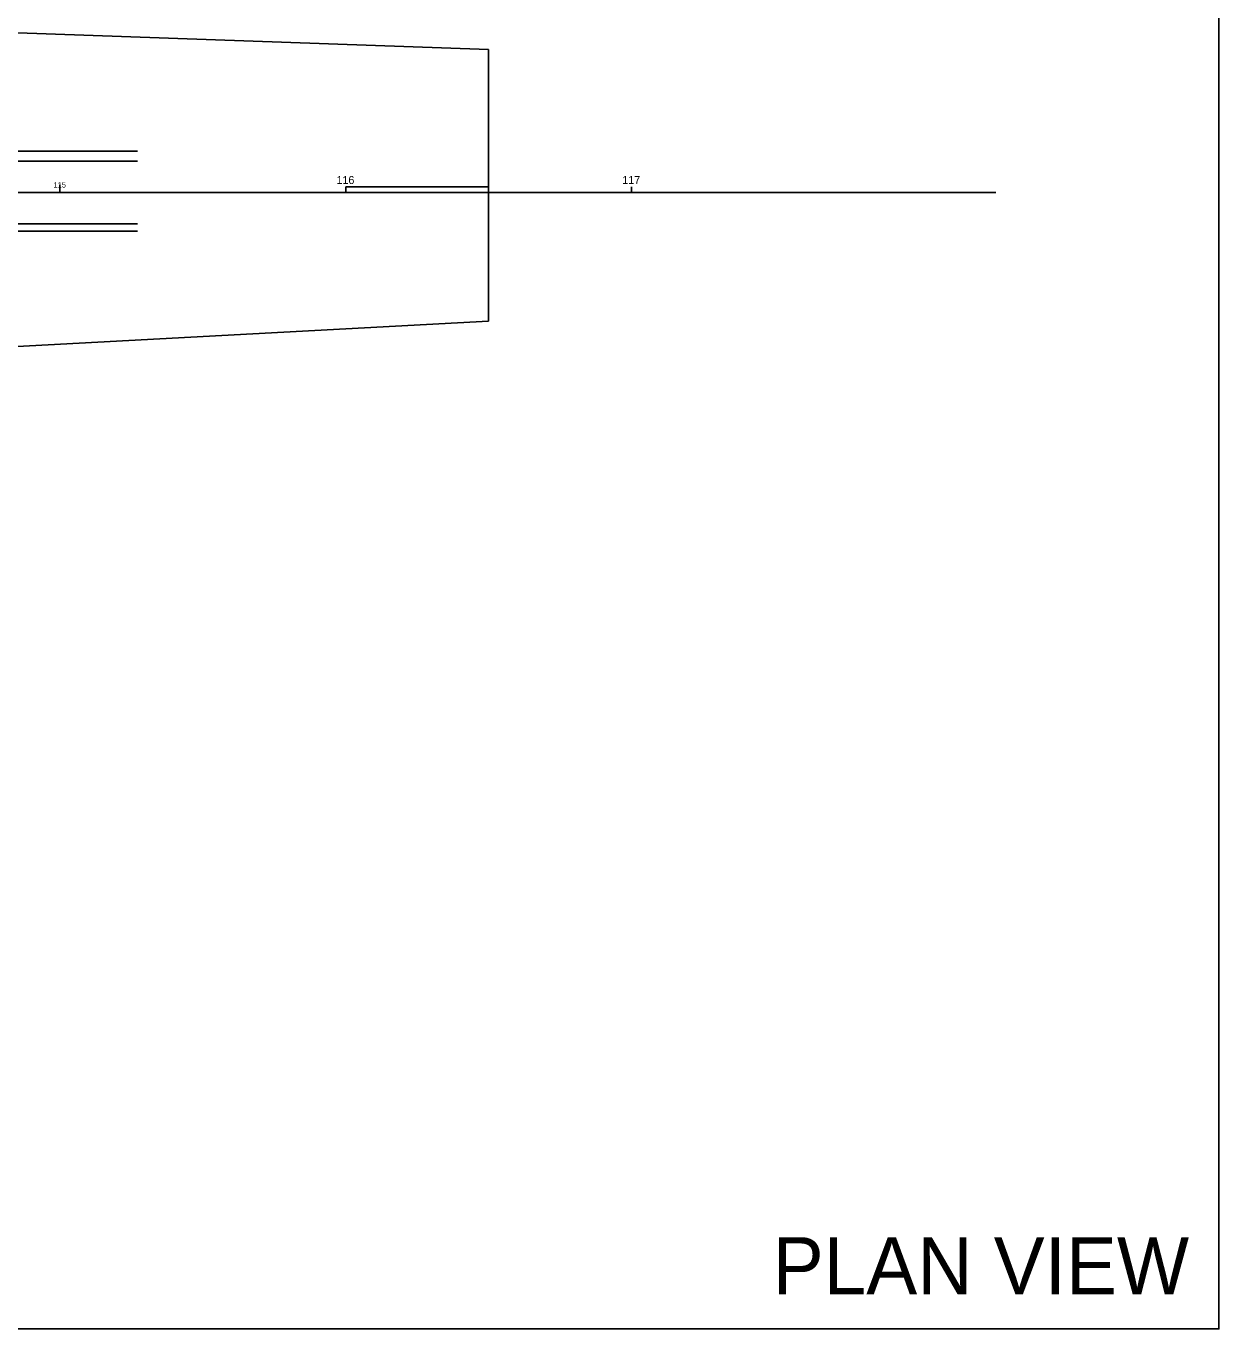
# Model space of a CAD drawing. Extents: x -1300 to 1299, y -770 to 1120.
# Drawn here: x 881.4 to 1298.8, y 27.4 to 483.1 of the extents above; entities that cross this region are included whole.
import ezdxf

# ---------------------------------------------------------------- set-up
doc = ezdxf.new("R2010")
doc.units = 0
for name, color, linetype in [('GE_X_CL_20', 7, 'Continuous'), ('PM_X_CL_Dashed', 7, 'Continuous'), ('PM_X_Edge_Line', 7, 'Continuous'), ('PV_P_Shoulder_Rumble_Strip', 7, 'Continuous'), ('PV_X_EOP', 7, 'Continuous'), ('RW_X_Fee_RW', 7, 'Continuous'), ('SC_Scratch1', 7, 'Continuous')]:
    doc.layers.add(name, color=color, linetype=linetype)

msp = doc.modelspace()

# ---------------------------------------------------------------- linework, layer by layer
at = {"layer": 'GE_X_CL_20'}
for p, q in [((391.46, 424.91), (920.48, 424.91)), ((893.26, 424.91), (893.26, 426.24))]:
    msp.add_line(p, q, dxfattribs=at)
at = {"layer": 'PM_X_CL_Dashed'}
msp.add_line((847.88, 424.91), (1220.7, 424.91), dxfattribs=at)
at = {"layer": 'PM_X_Edge_Line'}
for p, q in [((391.46, 435.91), (920.48, 435.91)), ((391.46, 413.91), (920.48, 413.91))]:
    msp.add_line(p, q, dxfattribs=at)
at = {"layer": 'PV_P_Shoulder_Rumble_Strip'}
msp.add_line((710.38, 424.91), (1093.26, 424.91), dxfattribs=at)
at = {"layer": 'PV_X_EOP'}
for points in [[(720.78, 442.91), (730.73, 442.91), (803.71, 439.41), (920.48, 439.41)], [(700.52, 406.91), (709.95, 406.91), (787.54, 411.41), (920.48, 411.41)]]:
    msp.add_lwpolyline(points, dxfattribs=at)
at = {"layer": 'RW_X_Fee_RW'}
for points in [[(193.26, 471.45), (543.26, 484.91), (763.26, 484.91), (1043.26, 474.91)], [(193.26, 378.37), (543.26, 364.91), (763.26, 364.91), (1043.26, 379.91)]]:
    msp.add_lwpolyline(points, dxfattribs=at)
at = {"layer": 'SC_Scratch1'}
for p, q in [((1043.26, 424.91), (1043.26, 474.91)), ((893.26, 426.24), (893.26, 427.58)), ((1093.26, 424.91), (920.48, 424.91)), ((993.26, 424.91), (993.26, 426.91)), ((993.26, 426.91), (1043.26, 426.91)), ((1043.26, 379.91), (1043.26, 424.91)), ((1093.26, 424.91), (1093.26, 426.91))]:
    msp.add_line(p, q, dxfattribs=at)
msp.add_lwpolyline([(68.08, 769.66), (1298.76, 769.66), (1298.76, 27.36), (68.08, 27.36)], close=True, dxfattribs=at)

# ---------------------------------------------------------------- texts
at = {"layer": 'GE_X_CL_20'}
msp.add_text('115', height=1.867, dxfattribs=at).set_placement((891.08, 426.64))
at = {"layer": 'SC_Scratch1'}
for s, height, p in [('116', 2.8, (990.05, 427.88)), ('117', 2.8, (1090.05, 427.88)), ('PLAN VIEW', 20, (1142.66, 39.45))]:
    msp.add_text(s, height=height, dxfattribs=at).set_placement(p)

doc.saveas('drawing.dxf')
